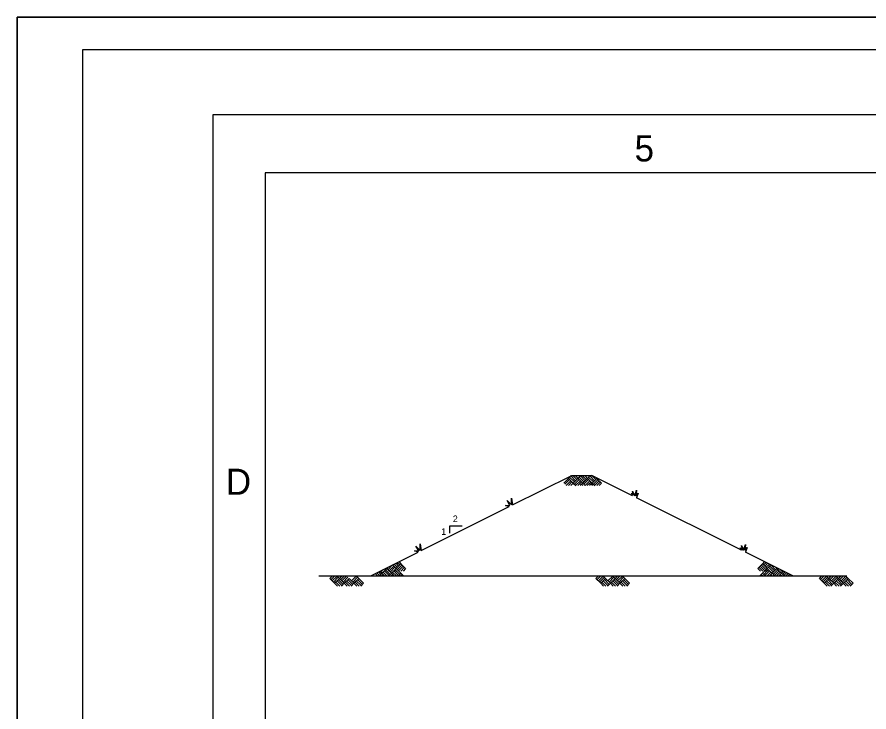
# Model space of a CAD drawing. Extents: x -0.04 to 2.79, y -0.02 to 1.81.
# Drawn here: x -0.042 to 0.502, y 1.369 to 1.813 of the extents above; entities that cross this region are included whole.
import ezdxf

# ---------------------------------------------------------------- set-up
doc = ezdxf.new("R2010")
doc.units = 0
for name, color, linetype in [('G-ANNO-NPLT', 7, 'Continuous'), ('G-ANNO-PLOT', 7, 'Continuous'), ('G-ANNO-TTLB', 7, 'Continuous'), ('Level 1', 7, 'Continuous')]:
    doc.layers.add(name, color=color, linetype=linetype)

msp = doc.modelspace()

# ---------------------------------------------------------------- linework, layer by layer
at = {"layer": 'G-ANNO-NPLT'}
msp.add_lwpolyline([(-0.04167, 1.8125), (2.79167, 1.8125), (2.79167, -0.02083), (-0.04167, -0.02083)], close=True, dxfattribs=at)
at = {"layer": 'G-ANNO-PLOT'}
for p, q in [((2.79167, 1.8125), (-0.04167, 1.8125)), ((-0.04167, 1.8125), (-0.04167, -0.02083))]:
    msp.add_line(p, q, dxfattribs=at)
msp.add_lwpolyline([(0, 0), (2.79167, 0), (2.79167, 1.79167), (0, 1.79167)], close=True, dxfattribs=at)
at = {"layer": 'G-ANNO-TTLB'}
for points in [[(0.2515, 1.75), (0.08333, 1.75), (0.08333, 0.04167)], [(0.08333, 0.04167), (2.72917, 0.04167), (2.72917, 1.75), (0.2515, 1.75)], [(0.11656, 0.08028), (2.69501, 0.08028), (2.69501, 1.71305), (0.11656, 1.71305)], [(0.11656, 1.71305), (0.11656, 0.08028)]]:
    msp.add_lwpolyline(points, dxfattribs=at)
at = {"layer": 'Level 1'}
for p, q in [((0.27433, 1.50112), (0.31213, 1.51998)), ((0.31007, 1.51813), (0.30707, 1.51513)), ((0.31083, 1.51738), (0.30782, 1.51438)), ((0.31158, 1.51663), (0.30857, 1.51362)), ((0.31185, 1.51991), (0.31007, 1.51813)), ((0.31007, 1.51813), (0.31308, 1.51513)), ((0.31007, 1.51813), (0.31308, 1.51513)), ((0.31083, 1.51889), (0.31383, 1.51588)), ((0.31158, 1.51964), (0.31459, 1.51663)), ((0.31213, 1.51998), (0.32497, 1.51998)), ((0.31288, 1.51991), (0.31534, 1.51738)), ((0.31609, 1.51813), (0.31308, 1.51513)), ((0.31691, 1.51738), (0.31383, 1.51438)), ((0.31438, 1.51991), (0.31917, 1.51513)), ((0.31766, 1.51663), (0.31459, 1.51362)), ((0.31787, 1.51991), (0.31609, 1.51813)), ((0.31691, 1.51889), (0.31992, 1.51588)), ((0.31766, 1.51964), (0.32067, 1.51663)), ((0.31889, 1.51991), (0.32142, 1.51738)), ((0.32217, 1.51813), (0.31917, 1.51513)), ((0.32292, 1.51738), (0.31992, 1.51438)), ((0.32046, 1.51991), (0.32217, 1.51813)), ((0.32368, 1.51663), (0.32067, 1.51362)), ((0.32395, 1.51991), (0.32217, 1.51813)), ((0.32217, 1.51813), (0.32525, 1.51513)), ((0.32292, 1.51889), (0.326, 1.51588)), ((0.32368, 1.51964), (0.32675, 1.51663)), ((0.35102, 1.50693), (0.32497, 1.51998)), ((0.32497, 1.51991), (0.3275, 1.51738)), ((0.32826, 1.51813), (0.32525, 1.51513)), ((0.32901, 1.51738), (0.326, 1.51438)), ((0.32976, 1.51663), (0.32675, 1.51362)), ((0.32785, 1.51854), (0.32826, 1.51813)), ((0.32826, 1.51813), (0.33126, 1.51513)), ((0.31233, 1.51588), (0.31001, 1.51349)), ((0.31308, 1.51513), (0.31151, 1.51349)), ((0.31308, 1.51513), (0.31472, 1.51349)), ((0.31841, 1.51588), (0.31602, 1.51349)), ((0.31917, 1.51513), (0.31752, 1.51349)), ((0.31917, 1.51513), (0.31752, 1.51349)), ((0.31766, 1.51362), (0.31773, 1.51349)), ((0.31841, 1.51438), (0.31923, 1.51349)), ((0.31917, 1.51513), (0.32081, 1.51349)), ((0.3245, 1.51588), (0.3221, 1.51349)), ((0.32525, 1.51513), (0.32361, 1.51349)), ((0.32525, 1.51513), (0.32361, 1.51349)), ((0.32368, 1.51362), (0.32381, 1.51349)), ((0.3245, 1.51438), (0.32532, 1.51349)), ((0.32525, 1.51513), (0.32682, 1.51349)), ((0.33051, 1.51588), (0.32812, 1.51349)), ((0.33126, 1.51513), (0.32962, 1.51349)), ((0.27371, 1.50118), (0.27371, 1.50542)), ((0.27371, 1.50542), (0.27433, 1.50118)), ((0.35108, 1.50693), (0.35026, 1.50857)), ((0.35026, 1.50857), (0.35156, 1.50734)), ((0.35156, 1.50734), (0.35095, 1.51)), ((0.35095, 1.51), (0.35232, 1.50706)), ((0.35232, 1.50706), (0.35355, 1.51062)), ((0.35355, 1.51062), (0.35307, 1.50706)), ((0.35307, 1.50706), (0.35464, 1.50877)), ((0.35464, 1.50877), (0.35348, 1.50576)), ((0.42053, 1.4722), (0.35348, 1.50576)), ((0.21623, 1.47207), (0.27234, 1.50009)), ((0.27002, 1.50084), (0.27275, 1.50084)), ((0.27234, 1.50016), (0.27002, 1.50084)), ((0.27275, 1.50084), (0.27091, 1.50392)), ((0.27091, 1.50392), (0.27371, 1.50118)), ((0.23434, 1.48307), (0.23434, 1.48779)), ((0.23434, 1.48779), (0.24234, 1.48779)), ((0.21459, 1.47179), (0.21274, 1.47487)), ((0.21274, 1.47487), (0.21555, 1.47207)), ((0.21555, 1.47207), (0.21555, 1.47637)), ((0.21555, 1.47637), (0.21616, 1.47207)), ((0.42053, 1.47213), (0.41971, 1.47378)), ((0.41971, 1.47378), (0.42108, 1.47254)), ((0.42108, 1.47254), (0.42046, 1.47521)), ((0.42046, 1.47521), (0.42183, 1.47227)), ((0.42183, 1.47227), (0.42306, 1.47583)), ((0.42306, 1.47583), (0.42251, 1.47227)), ((0.42251, 1.47227), (0.42415, 1.47398)), ((0.42415, 1.47398), (0.42292, 1.47097)), ((0.18397, 1.45587), (0.21418, 1.47104)), ((0.21185, 1.47179), (0.21459, 1.47179)), ((0.21418, 1.47104), (0.21185, 1.47179)), ((0.45313, 1.45587), (0.42292, 1.47097)), ((0.19791, 1.46284), (0.1949, 1.45983)), ((0.19866, 1.46209), (0.19566, 1.45908)), ((0.19784, 1.46291), (0.20017, 1.46058)), ((0.19887, 1.46339), (0.20092, 1.46134)), ((0.19989, 1.46393), (0.20167, 1.46209)), ((0.19989, 1.46277), (0.19989, 1.46277)), ((0.20317, 1.46359), (0.20017, 1.46058)), ((0.20092, 1.46441), (0.20242, 1.46284)), ((0.20393, 1.46284), (0.20092, 1.45983)), ((0.20468, 1.46209), (0.20167, 1.45908)), ((0.20188, 1.46496), (0.20317, 1.46359)), ((0.20317, 1.46359), (0.20618, 1.46058)), ((0.43386, 1.46359), (0.43085, 1.46058)), ((0.43235, 1.46209), (0.43536, 1.45908)), ((0.43311, 1.46284), (0.43618, 1.45983)), ((0.43516, 1.46496), (0.43386, 1.46359)), ((0.43386, 1.46359), (0.43693, 1.46058)), ((0.43618, 1.46441), (0.43461, 1.46284)), ((0.43721, 1.46393), (0.43536, 1.46209)), ((0.43823, 1.46339), (0.43618, 1.46134)), ((0.43919, 1.46291), (0.43693, 1.46058)), ((0.43721, 1.46277), (0.43721, 1.46277)), ((0.43844, 1.46209), (0.44144, 1.45908)), ((0.43919, 1.46284), (0.4422, 1.45983)), ((0.18684, 1.45737), (0.1882, 1.45594)), ((0.18779, 1.45785), (0.18964, 1.45607)), ((0.18882, 1.4584), (0.19039, 1.45682)), ((0.19114, 1.45758), (0.1895, 1.45594)), ((0.18985, 1.45887), (0.19278, 1.45594)), ((0.19196, 1.45997), (0.19039, 1.4584)), ((0.19101, 1.45833), (0.19101, 1.45833)), ((0.1919, 1.45682), (0.19101, 1.45594)), ((0.19285, 1.45935), (0.19114, 1.45758)), ((0.1919, 1.45833), (0.19429, 1.45594)), ((0.19415, 1.46058), (0.19251, 1.45894)), ((0.19415, 1.46058), (0.19251, 1.45894)), ((0.19265, 1.45908), (0.19566, 1.45607)), ((0.19265, 1.45908), (0.19272, 1.45894)), ((0.1934, 1.45983), (0.19422, 1.45894)), ((0.19381, 1.46086), (0.19415, 1.46058)), ((0.19388, 1.45935), (0.19641, 1.45682)), ((0.19401, 1.45983), (0.19401, 1.45983)), ((0.19497, 1.46147), (0.19415, 1.46058)), ((0.19415, 1.46058), (0.19572, 1.45894)), ((0.19483, 1.4614), (0.1949, 1.46134)), ((0.19545, 1.45935), (0.19716, 1.45758)), ((0.19716, 1.45758), (0.19552, 1.45594)), ((0.19941, 1.46134), (0.19648, 1.4584)), ((0.19791, 1.45682), (0.19702, 1.45594)), ((0.19894, 1.45935), (0.19716, 1.45758)), ((0.19716, 1.45758), (0.1988, 1.45594)), ((0.19791, 1.46175), (0.19791, 1.46175)), ((0.19791, 1.45833), (0.2003, 1.45594)), ((0.20017, 1.46058), (0.19853, 1.45894)), ((0.20017, 1.46058), (0.19853, 1.45894)), ((0.19866, 1.45908), (0.20167, 1.45607)), ((0.19866, 1.45908), (0.1988, 1.45894)), ((0.19941, 1.45983), (0.2003, 1.45894)), ((0.19996, 1.45935), (0.20242, 1.45682)), ((0.20017, 1.46058), (0.20181, 1.45894)), ((0.20147, 1.45935), (0.20324, 1.45758)), ((0.20324, 1.45758), (0.2016, 1.45594)), ((0.20543, 1.46134), (0.20311, 1.45894)), ((0.20399, 1.45682), (0.20311, 1.45594)), ((0.20324, 1.45758), (0.20481, 1.45594)), ((0.20618, 1.46058), (0.20461, 1.45894)), ((0.43085, 1.46058), (0.43249, 1.45894)), ((0.4316, 1.46134), (0.43399, 1.45894)), ((0.43386, 1.45758), (0.43222, 1.45594)), ((0.43311, 1.45682), (0.43399, 1.45594)), ((0.43563, 1.45935), (0.43386, 1.45758)), ((0.43386, 1.45758), (0.4355, 1.45594)), ((0.43714, 1.45935), (0.43461, 1.45682)), ((0.43693, 1.46058), (0.43529, 1.45894)), ((0.43837, 1.45908), (0.43536, 1.45607)), ((0.43769, 1.45983), (0.4368, 1.45894)), ((0.43912, 1.45833), (0.4368, 1.45594)), ((0.43693, 1.46058), (0.43851, 1.45894)), ((0.43693, 1.46058), (0.43851, 1.45894)), ((0.43769, 1.46134), (0.44056, 1.4584)), ((0.43816, 1.45935), (0.43994, 1.45758)), ((0.43844, 1.45908), (0.4383, 1.45894)), ((0.43994, 1.45758), (0.4383, 1.45594)), ((0.43912, 1.45682), (0.44001, 1.45594)), ((0.43919, 1.46175), (0.43919, 1.46175)), ((0.44165, 1.45935), (0.43994, 1.45758)), ((0.43994, 1.45758), (0.44151, 1.45594)), ((0.44315, 1.45935), (0.44069, 1.45682)), ((0.44295, 1.46058), (0.44131, 1.45894)), ((0.44445, 1.45908), (0.44144, 1.45607)), ((0.44206, 1.46147), (0.44295, 1.46058)), ((0.4422, 1.4614), (0.4422, 1.46134)), ((0.4437, 1.45983), (0.44281, 1.45894)), ((0.4452, 1.45833), (0.44281, 1.45594)), ((0.44322, 1.46086), (0.44295, 1.46058)), ((0.44295, 1.46058), (0.44459, 1.45894)), ((0.44295, 1.46058), (0.44459, 1.45894)), ((0.44309, 1.45983), (0.44309, 1.45983)), ((0.44418, 1.45935), (0.44596, 1.45758)), ((0.44445, 1.45908), (0.44432, 1.45894)), ((0.44725, 1.45887), (0.44432, 1.45594)), ((0.44507, 1.45997), (0.44671, 1.4584)), ((0.4452, 1.45682), (0.44609, 1.45594)), ((0.44596, 1.45758), (0.4476, 1.45594)), ((0.44609, 1.45833), (0.44609, 1.45833)), ((0.44821, 1.4584), (0.44671, 1.45682)), ((0.44924, 1.45785), (0.44746, 1.45607)), ((0.45026, 1.45737), (0.44883, 1.45594)), ((0.45129, 1.45689), (0.45033, 1.45594)), ((0.15075, 1.45587), (0.48758, 1.45587)), ((0.15793, 1.4543), (0.15957, 1.45587)), ((0.16093, 1.45115), (0.15793, 1.4543)), ((0.15868, 1.45347), (0.16107, 1.45587)), ((0.15943, 1.45272), (0.16251, 1.4558)), ((0.16018, 1.45197), (0.16326, 1.45505)), ((0.16093, 1.45115), (0.16401, 1.4543)), ((0.16278, 1.44937), (0.16093, 1.45115)), ((0.16428, 1.44937), (0.16175, 1.45197)), ((0.16401, 1.4543), (0.16237, 1.45587)), ((0.16558, 1.44965), (0.16251, 1.45272)), ((0.16633, 1.4504), (0.16326, 1.45347)), ((0.16483, 1.45505), (0.16394, 1.45587)), ((0.16401, 1.4543), (0.16565, 1.45587)), ((0.16401, 1.4543), (0.16565, 1.45587)), ((0.16708, 1.45115), (0.16401, 1.4543)), ((0.16483, 1.45347), (0.16722, 1.45587)), ((0.16531, 1.44937), (0.16708, 1.45115)), ((0.16558, 1.45272), (0.16859, 1.4558)), ((0.16633, 1.45197), (0.16941, 1.45505)), ((0.16708, 1.45115), (0.17016, 1.4543)), ((0.16886, 1.44937), (0.16708, 1.45115)), ((0.17043, 1.44937), (0.16784, 1.45197)), ((0.17173, 1.44965), (0.16859, 1.45272)), ((0.17248, 1.4504), (0.16941, 1.45347)), ((0.17501, 1.44937), (0.17016, 1.4543)), ((0.17146, 1.44937), (0.17324, 1.45115)), ((0.17173, 1.45272), (0.17474, 1.4558)), ((0.17248, 1.45197), (0.17556, 1.45505)), ((0.17324, 1.45115), (0.17631, 1.4543)), ((0.17659, 1.44937), (0.17399, 1.45197)), ((0.17631, 1.4543), (0.17467, 1.45587)), ((0.17782, 1.44965), (0.17474, 1.45272)), ((0.17864, 1.4504), (0.17556, 1.45347)), ((0.17939, 1.45115), (0.17631, 1.4543)), ((0.17761, 1.44937), (0.17939, 1.45115)), ((0.19265, 1.45607), (0.19251, 1.45594)), ((0.19866, 1.45607), (0.19853, 1.45594)), ((0.20475, 1.45607), (0.20461, 1.45594)), ((0.32764, 1.4543), (0.32928, 1.45587)), ((0.33065, 1.45115), (0.32764, 1.4543)), ((0.32839, 1.45347), (0.33078, 1.45587)), ((0.32914, 1.45272), (0.33222, 1.4558)), ((0.3299, 1.45197), (0.33297, 1.45505)), ((0.33065, 1.45115), (0.33372, 1.4543)), ((0.33249, 1.44937), (0.33065, 1.45115)), ((0.334, 1.44937), (0.33147, 1.45197)), ((0.33372, 1.4543), (0.33208, 1.45587)), ((0.3353, 1.44965), (0.33222, 1.45272)), ((0.33605, 1.4504), (0.33297, 1.45347)), ((0.3368, 1.45115), (0.33372, 1.4543)), ((0.33502, 1.44937), (0.3368, 1.45115)), ((0.3353, 1.45272), (0.3383, 1.4558)), ((0.33605, 1.45197), (0.33912, 1.45505)), ((0.3368, 1.45115), (0.33988, 1.4543)), ((0.33858, 1.44937), (0.3368, 1.45115)), ((0.34015, 1.44937), (0.33755, 1.45197)), ((0.33988, 1.4543), (0.33824, 1.45587)), ((0.34145, 1.44965), (0.3383, 1.45272)), ((0.3422, 1.4504), (0.33912, 1.45347)), ((0.3407, 1.45505), (0.33981, 1.45587)), ((0.33988, 1.4543), (0.34152, 1.45587)), ((0.33988, 1.4543), (0.34152, 1.45587)), ((0.34473, 1.44937), (0.33988, 1.4543)), ((0.3407, 1.45347), (0.34309, 1.45587)), ((0.34117, 1.44937), (0.34295, 1.45115)), ((0.34145, 1.4558), (0.34131, 1.45587)), ((0.34145, 1.45272), (0.34445, 1.4558)), ((0.3422, 1.45197), (0.34528, 1.45505)), ((0.34295, 1.45115), (0.34603, 1.4543)), ((0.3463, 1.44937), (0.3437, 1.45197)), ((0.34603, 1.4543), (0.34439, 1.45587)), ((0.34753, 1.44965), (0.34445, 1.45272)), ((0.34835, 1.4504), (0.34528, 1.45347)), ((0.3491, 1.45115), (0.34603, 1.4543)), ((0.34733, 1.44937), (0.3491, 1.45115)), ((0.43235, 1.45607), (0.43249, 1.45594)), ((0.43837, 1.45607), (0.43851, 1.45594)), ((0.44445, 1.45607), (0.44459, 1.45594)), ((0.45122, 1.45573), (0.45122, 1.45573)), ((0.47015, 1.4543), (0.47179, 1.45587)), ((0.47316, 1.45115), (0.47015, 1.4543)), ((0.4709, 1.45347), (0.4733, 1.45587)), ((0.47166, 1.45272), (0.47473, 1.4558)), ((0.47241, 1.45197), (0.47548, 1.45505)), ((0.47316, 1.45115), (0.47624, 1.4543)), ((0.47501, 1.44937), (0.47316, 1.45115)), ((0.47651, 1.44937), (0.47398, 1.45197)), ((0.47624, 1.4543), (0.47459, 1.45587)), ((0.47781, 1.44965), (0.47473, 1.45272)), ((0.47856, 1.4504), (0.47548, 1.45347)), ((0.47706, 1.45505), (0.47617, 1.45587)), ((0.47624, 1.4543), (0.47788, 1.45587)), ((0.47624, 1.4543), (0.47788, 1.45587)), ((0.47931, 1.45115), (0.47624, 1.4543)), ((0.47706, 1.45347), (0.47945, 1.45587)), ((0.47753, 1.44937), (0.47931, 1.45115)), ((0.47781, 1.4558), (0.47767, 1.45587)), ((0.47781, 1.45272), (0.48081, 1.4558)), ((0.47856, 1.45197), (0.48164, 1.45505)), ((0.47931, 1.45115), (0.48239, 1.4543)), ((0.48109, 1.44937), (0.47931, 1.45115)), ((0.48266, 1.44937), (0.48006, 1.45197)), ((0.48239, 1.4543), (0.48075, 1.45587)), ((0.48396, 1.44965), (0.48081, 1.45272)), ((0.48471, 1.4504), (0.48164, 1.45347)), ((0.48321, 1.45505), (0.48232, 1.45587)), ((0.48239, 1.4543), (0.48403, 1.45587)), ((0.48239, 1.4543), (0.48403, 1.45587)), ((0.48724, 1.44937), (0.48239, 1.4543)), ((0.48321, 1.45347), (0.4856, 1.45587)), ((0.48369, 1.44937), (0.48546, 1.45115)), ((0.48396, 1.4558), (0.48382, 1.45587)), ((0.48396, 1.45272), (0.48697, 1.4558)), ((0.48471, 1.45197), (0.48779, 1.45505)), ((0.48546, 1.45115), (0.48854, 1.4543)), ((0.48881, 1.44937), (0.48621, 1.45197)), ((0.48854, 1.4543), (0.4869, 1.45587)), ((0.49004, 1.44965), (0.48697, 1.45272)), ((0.49086, 1.4504), (0.48779, 1.45347)), ((0.49161, 1.45115), (0.48854, 1.4543)), ((0.48984, 1.44937), (0.49161, 1.45115))]:
    msp.add_line(p, q, dxfattribs=at)

# ---------------------------------------------------------------- texts
at = {"layer": 'G-ANNO-TTLB'}
for s, p in [('5', (0.35226, 1.72035)), ('D', (0.09154, 1.50763))]:
    msp.add_text(s, height=0.01667, dxfattribs=at).set_placement(p)
at = {"layer": 'Level 1'}
for s, p in [('2', (0.23632, 1.49018)), ('1', (0.22894, 1.48205))]:
    msp.add_text(s, height=0.00424, dxfattribs=at).set_placement(p)

doc.saveas('drawing.dxf')
